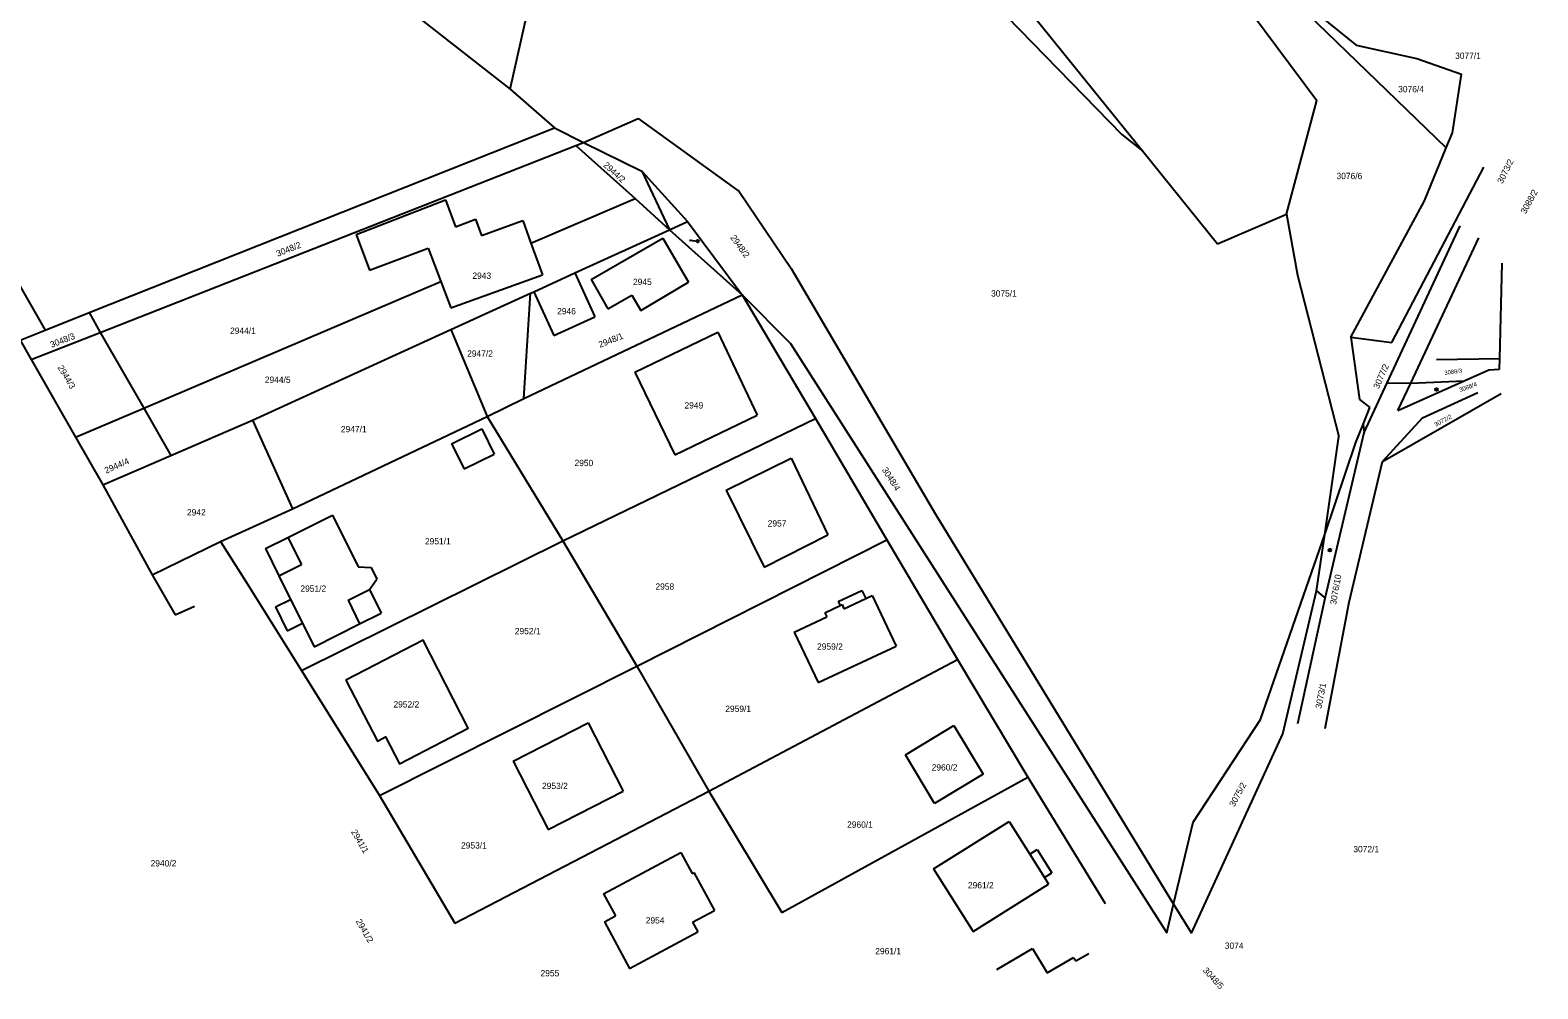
# Model space of a CAD drawing. Extents: x -722132 to -721608, y -1046877 to -1046449.
# Drawn here: x -721811.3 to -721608, y -1046875.1 to -1046745.8 of the extents above; entities that cross this region are included whole.
import ezdxf

# ---------------------------------------------------------------- set-up
doc = ezdxf.new("R2010")
doc.units = 0
for name, color, linetype in [('Vrstva 1', 7, 'Continuous'), ('Vrstva 16', 7, 'Continuous'), ('Vrstva 18', 7, 'Continuous'), ('Vrstva 19', 7, 'Continuous'), ('Vrstva 4', 7, 'Continuous'), ('Vrstva 6', 7, 'Continuous')]:
    doc.layers.add(name, color=color, linetype=linetype)

msp = doc.modelspace()

# ---------------------------------------------------------------- linework, layer by layer
at = {"layer": 'Vrstva 1'}
for p, q in [((-721693.28, -1046843.54), (-721686.72, -1046839.58)), ((-721686.72, -1046839.58), (-721682.77, -1046846.14)), ((-721689.35, -1046850.08), (-721693.28, -1046843.54)), ((-721682.77, -1046846.14), (-721689.35, -1046850.08))]:
    msp.add_line(p, q, dxfattribs=at)
for points in [[(-721796.01, -1046715.1), (-721746.59, -1046753.73)], [(-721684.82, -1046732.93), (-721661.26, -1046762.13)], [(-721746.59, -1046753.73), (-721742.65, -1046736.09)], [(-721686.47, -1046736.84), (-721664.08, -1046759.87)], [(-721651.87, -1046736.33), (-721637.78, -1046755.26)], [(-721645.76, -1046737.04), (-721620.31, -1046761.66)], [(-721645.76, -1046737.04), (-721632.49, -1046747.8)], [(-721831.5, -1046747.47), (-721809.33, -1046786.25)], [(-721632.49, -1046747.8), (-721624.3, -1046749.62)], [(-721624.3, -1046749.62), (-721618.24, -1046751.72)], [(-721619.47, -1046759.63), (-721618.24, -1046751.72)], [(-721746.59, -1046753.73), (-721740.59, -1046758.98)], [(-721641.86, -1046770.61), (-721637.78, -1046755.26)], [(-721803.37, -1046783.89), (-721740.59, -1046758.98)], [(-721740.59, -1046758.98), (-721736.69, -1046760.93)], [(-721736.69, -1046760.93), (-721729.32, -1046757.69)], [(-721729.32, -1046757.69), (-721715.68, -1046767.54)], [(-721801.9, -1046786.57), (-721737.71, -1046761.33)], [(-721737.71, -1046761.33), (-721736.69, -1046760.93)], [(-721737.71, -1046761.33), (-721729.73, -1046768.51)], [(-721736.69, -1046760.93), (-721728.84, -1046764.8)], [(-721664.08, -1046759.87), (-721661.26, -1046762.13)], [(-721620.31, -1046761.66), (-721619.47, -1046759.63)], [(-721661.26, -1046762.13), (-721651.19, -1046774.61)], [(-721623.26, -1046768.81), (-721620.31, -1046761.66)], [(-721728.84, -1046764.8), (-721722.67, -1046771.6)], [(-721627.66, -1046787.93), (-721615.25, -1046764.26)], [(-721767.37, -1046773.33), (-721755.29, -1046768.66)], [(-721755.29, -1046768.66), (-721753.94, -1046772.3)], [(-721729.73, -1046768.51), (-721725.08, -1046772.7)], [(-721715.68, -1046767.54), (-721708.67, -1046777.94)], [(-721633.18, -1046787.18), (-721623.26, -1046768.81)], [(-721753.94, -1046772.3), (-721751.24, -1046771.3)], [(-721751.24, -1046771.3), (-721750.46, -1046773.48)], [(-721750.46, -1046773.48), (-721744.88, -1046771.48)], [(-721744.88, -1046771.48), (-721743.79, -1046774.5)], [(-721651.19, -1046774.61), (-721641.86, -1046770.61)], [(-721641.86, -1046770.61), (-721640.4, -1046778.83)], [(-721767.37, -1046773.33), (-721765.54, -1046778.18)], [(-721737.88, -1046778.54), (-721725.08, -1046772.7)], [(-721725.08, -1046772.7), (-721722.67, -1046771.6)], [(-721725.08, -1046772.7), (-721715.3, -1046781.5)], [(-721722.67, -1046771.6), (-721715.3, -1046781.5)], [(-721628.27, -1046793.34), (-721618.45, -1046772.19)], [(-721765.54, -1046778.18), (-721757.63, -1046775.19)], [(-721757.63, -1046775.19), (-721755.93, -1046779.68)], [(-721743.79, -1046774.5), (-721742.23, -1046778.81)], [(-721735.65, -1046779.44), (-721725.98, -1046773.84)], [(-721725.98, -1046773.84), (-721722.54, -1046779.77)], [(-721625.1, -1046793.41), (-721615.9, -1046773.8)], [(-721613.11, -1046790.06), (-721612.77, -1046777.21)], [(-721754.57, -1046783.26), (-721742.23, -1046778.81)], [(-721743.4, -1046781.06), (-721737.88, -1046778.54)], [(-721737.88, -1046778.54), (-721735.17, -1046784.47)], [(-721735.65, -1046779.44), (-721733.41, -1046783.36)], [(-721708.67, -1046777.94), (-721689.23, -1046811.06)], [(-721640.4, -1046778.83), (-721634.82, -1046800.6)], [(-721755.93, -1046779.68), (-721754.57, -1046783.26)], [(-721754.61, -1046786.18), (-721743.84, -1046781.26)], [(-721744.72, -1046795.45), (-721743.84, -1046781.26)], [(-721744.72, -1046795.45), (-721715.3, -1046781.5)], [(-721743.84, -1046781.26), (-721743.4, -1046781.06)], [(-721743.4, -1046781.06), (-721740.69, -1046786.99)], [(-721733.41, -1046783.36), (-721730.18, -1046781.51)], [(-721730.18, -1046781.51), (-721728.97, -1046783.61)], [(-721728.97, -1046783.61), (-721722.54, -1046779.77)], [(-721715.3, -1046781.5), (-721705.42, -1046798.17)], [(-721809.33, -1046786.25), (-721803.37, -1046783.89)], [(-721803.37, -1046783.89), (-721801.9, -1046786.57)], [(-721740.69, -1046786.99), (-721735.17, -1046784.47)], [(-721812.66, -1046787.58), (-721809.33, -1046786.25)], [(-721812.66, -1046787.58), (-721811.2, -1046790.23)], [(-721811.2, -1046790.23), (-721801.9, -1046786.57)], [(-721781.34, -1046798.38), (-721754.61, -1046786.18)], [(-721729.78, -1046791.91), (-721718.58, -1046786.53)], [(-721718.58, -1046786.53), (-721713.25, -1046797.7)], [(-721633.18, -1046787.18), (-721627.66, -1046787.93)], [(-721633.18, -1046787.18), (-721632.01, -1046795.59)], [(-721811.2, -1046790.23), (-721805.2, -1046800.68)], [(-721621.64, -1046790.19), (-721613.11, -1046790.06)], [(-721617.9, -1046793.1), (-721614.58, -1046791.61)], [(-721614.58, -1046791.61), (-721613.15, -1046791.51)], [(-721613.15, -1046791.51), (-721613.11, -1046790.06)], [(-721729.78, -1046791.91), (-721724.37, -1046803.08)], [(-721631.39, -1046800.05), (-721628.27, -1046793.34)], [(-721626.83, -1046797.11), (-721617.9, -1046793.1)], [(-721626.83, -1046797.11), (-721625.1, -1046793.41)], [(-721625.1, -1046793.41), (-721617.9, -1046793.1)], [(-721749.71, -1046797.89), (-721744.72, -1046795.45)], [(-721623.53, -1046798.09), (-721616.06, -1046794.65)], [(-721775.95, -1046810.37), (-721749.71, -1046797.89)], [(-721749.71, -1046797.89), (-721739.5, -1046814.68)], [(-721724.37, -1046803.08), (-721713.25, -1046797.7)], [(-721792.35, -1046803.14), (-721781.34, -1046798.38)], [(-721781.34, -1046798.38), (-721775.95, -1046810.37)], [(-721739.5, -1046814.68), (-721705.42, -1046798.17)], [(-721705.42, -1046798.17), (-721695.78, -1046814.53)], [(-721631.54, -1046798.97), (-721631.39, -1046800.05)], [(-721628.92, -1046803.96), (-721623.53, -1046798.09)], [(-721805.2, -1046800.68), (-721801.51, -1046807.1)], [(-721636.71, -1046813.8), (-721634.82, -1046800.6)], [(-721636.64, -1046822.42), (-721631.39, -1046800.05)], [(-721801.51, -1046807.1), (-721792.35, -1046803.14)], [(-721717.46, -1046807.83), (-721708.66, -1046803.51)], [(-721708.66, -1046803.51), (-721703.72, -1046813.87)], [(-721633.43, -1046822.95), (-721628.92, -1046803.96)], [(-721801.51, -1046807.1), (-721794.88, -1046819.26)], [(-721717.46, -1046807.83), (-721712.34, -1046818.2)], [(-721785.64, -1046814.77), (-721775.95, -1046810.37)], [(-721776.56, -1046814.2), (-721770.53, -1046811.2)], [(-721770.53, -1046811.2), (-721767.09, -1046818.16)], [(-721689.23, -1046811.06), (-721657.09, -1046863.66)], [(-721779.59, -1046815.71), (-721776.56, -1046814.2)], [(-721712.34, -1046818.2), (-721703.72, -1046813.87)], [(-721645.36, -1046838.78), (-721636.71, -1046813.8)], [(-721637.8, -1046821.42), (-721636.71, -1046813.8)], [(-721794.88, -1046819.26), (-721785.64, -1046814.77)], [(-721785.64, -1046814.77), (-721782.17, -1046820.29)], [(-721779.59, -1046815.71), (-721777.77, -1046819.38)], [(-721774.72, -1046832.15), (-721739.5, -1046814.68)], [(-721739.5, -1046814.68), (-721729.49, -1046831.56)], [(-721729.49, -1046831.56), (-721695.78, -1046814.53)], [(-721695.78, -1046814.53), (-721686.26, -1046830.68)], [(-721767.09, -1046818.16), (-721765.35, -1046818.25)], [(-721765.35, -1046818.25), (-721764.58, -1046819.82)], [(-721794.88, -1046819.26), (-721791.78, -1046824.67)], [(-721782.17, -1046820.29), (-721774.72, -1046832.15)], [(-721777.77, -1046819.38), (-721776.2, -1046822.56)], [(-721765.56, -1046821.25), (-721764.58, -1046819.82)], [(-721765.56, -1046821.25), (-721763.99, -1046824.43)], [(-721702.35, -1046822.86), (-721699.14, -1046821.36)], [(-721699.14, -1046821.36), (-721698.63, -1046822.44)], [(-721698.63, -1046822.44), (-721697.74, -1046822.02)], [(-721697.74, -1046822.02), (-721694.5, -1046828.86)], [(-721642.34, -1046840.71), (-721637.8, -1046821.42)], [(-721637.8, -1046821.42), (-721636.64, -1046822.42)], [(-721778.26, -1046823.58), (-721776.2, -1046822.56)], [(-721778.26, -1046823.58), (-721776.66, -1046826.81)], [(-721704.14, -1046824.36), (-721702.09, -1046823.4)], [(-721704.14, -1046824.36), (-721703.88, -1046824.91)], [(-721702.35, -1046822.86), (-721702.09, -1046823.4)], [(-721640.33, -1046839.32), (-721636.64, -1046822.42)], [(-721636.63, -1046839.98), (-721633.43, -1046822.95)], [(-721776.66, -1046826.81), (-721774.6, -1046825.79)], [(-721774.6, -1046825.79), (-721773.04, -1046828.95)], [(-721773.04, -1046828.95), (-721766.89, -1046825.88)], [(-721766.89, -1046825.88), (-721763.99, -1046824.43)], [(-721708.28, -1046826.98), (-721703.88, -1046824.91)], [(-721768.76, -1046833.45), (-721764.48, -1046841.67), (-721763.41, -1046841.12), (-721761.51, -1046844.76), (-721752.23, -1046839.92), (-721758.34, -1046828.08), (-721768.76, -1046833.45)], [(-721708.28, -1046826.98), (-721705.05, -1046833.79)], [(-721705.05, -1046833.79), (-721694.5, -1046828.86)], [(-721774.72, -1046832.15), (-721764.2, -1046849)], [(-721764.2, -1046849), (-721729.49, -1046831.56)], [(-721729.49, -1046831.56), (-721719.77, -1046848.42)], [(-721719.77, -1046848.42), (-721686.26, -1046830.68)], [(-721686.26, -1046830.68), (-721676.74, -1046846.55)], [(-721746.2, -1046844.38), (-721736.06, -1046839.2)], [(-721736.06, -1046839.2), (-721731.34, -1046848.45)], [(-721654.46, -1046852.63), (-721645.36, -1046838.78)], [(-721654.68, -1046867.6), (-721642.34, -1046840.71)], [(-721746.2, -1046844.38), (-721741.48, -1046853.62)], [(-721709.96, -1046864.8), (-721676.74, -1046846.55)], [(-721676.74, -1046846.55), (-721666.33, -1046863.6)], [(-721741.48, -1046853.62), (-721731.34, -1046848.45)], [(-721719.77, -1046848.42), (-721709.96, -1046864.8)], [(-721689.47, -1046858.91), (-721679.27, -1046852.51)], [(-721679.27, -1046852.51), (-721676.51, -1046856.91)], [(-721657.09, -1046863.66), (-721654.46, -1046852.63)], [(-721733.98, -1046862.27), (-721723.58, -1046856.69)], [(-721723.58, -1046856.69), (-721722.05, -1046859.54)], [(-721676.51, -1046856.91), (-721675.52, -1046856.29)], [(-721675.52, -1046856.29), (-721673.53, -1046859.46)], [(-721689.47, -1046858.91), (-721684.13, -1046867.38)], [(-721722.05, -1046859.54), (-721721.79, -1046859.4)], [(-721721.79, -1046859.4), (-721719.04, -1046864.53)], [(-721684.13, -1046867.38), (-721673.95, -1046860.99)], [(-721674.52, -1046860.08), (-721673.53, -1046859.46)], [(-721674.52, -1046860.08), (-721673.95, -1046860.99)], [(-721733.98, -1046862.27), (-721732.39, -1046865.25)], [(-721721.98, -1046866.11), (-721719.04, -1046864.53)], [(-721657.09, -1046863.66), (-721654.68, -1046867.6)], [(-721733.87, -1046866.04), (-721732.39, -1046865.25)], [(-721733.87, -1046866.04), (-721730.49, -1046872.35)], [(-721721.98, -1046866.11), (-721721.28, -1046867.41)], [(-721730.49, -1046872.35), (-721721.28, -1046867.41)], [(-721680.93, -1046872.47), (-721676.11, -1046869.64)], [(-721676.11, -1046869.64), (-721674.17, -1046872.96)], [(-721674.17, -1046872.96), (-721670.58, -1046870.86)], [(-721670.58, -1046870.86), (-721670.3, -1046871.33)], [(-721670.3, -1046871.33), (-721668.55, -1046870.32)]]:
    msp.add_lwpolyline(points, dxfattribs=at)
at = {"layer": 'Vrstva 16'}
for points in [[(-721722.38, -1046774.12), (-721721.3, -1046774.23)], [(-721621.88, -1046794.22), (-721621.63, -1046794.26)], [(-721636.15, -1046815.75), (-721636.01, -1046815.94)]]:
    msp.add_lwpolyline(points, dxfattribs=at)
for centre in [(-721721.3, -1046774.23), (-721621.63, -1046794.26), (-721636.01, -1046815.94)]:
    msp.add_circle(centre, 0.175, dxfattribs=at)
at = {"layer": 'Vrstva 4'}
for points in [[(-721728.84, -1046764.8), (-721725.08, -1046772.7)], [(-721754.49, -1046801.57), (-721750.43, -1046799.56)], [(-721750.43, -1046799.56), (-721748.74, -1046802.98)], [(-721754.49, -1046801.57), (-721752.8, -1046804.95)], [(-721752.8, -1046804.95), (-721748.74, -1046802.98)], [(-721776.56, -1046814.2), (-721774.74, -1046817.88)], [(-721777.77, -1046819.38), (-721774.74, -1046817.88)], [(-721768.46, -1046822.69), (-721765.56, -1046821.25)], [(-721776.2, -1046822.56), (-721774.6, -1046825.79)], [(-721768.46, -1046822.69), (-721766.89, -1046825.88)], [(-721702.09, -1046823.4), (-721701.82, -1046823.27)], [(-721701.82, -1046823.27), (-721701.56, -1046823.82)], [(-721701.56, -1046823.82), (-721698.63, -1046822.44)], [(-721676.51, -1046856.91), (-721674.52, -1046860.08)]]:
    msp.add_lwpolyline(points, dxfattribs=at)
at = {"layer": 'Vrstva 6'}
for points in [[(-721743.79, -1046774.5), (-721729.73, -1046768.51)], [(-721796.02, -1046796.77), (-721755.93, -1046779.68)], [(-721715.3, -1046781.5), (-721708.76, -1046788.03)], [(-721801.9, -1046786.57), (-721796.02, -1046796.77)], [(-721754.61, -1046786.18), (-721749.71, -1046797.89)], [(-721708.76, -1046788.03), (-721658.02, -1046867.55)], [(-721628.27, -1046793.34), (-721625.1, -1046793.41)], [(-721632.01, -1046795.59), (-721630.64, -1046796.7)], [(-721628.92, -1046803.96), (-721612.93, -1046794.81)], [(-721805.2, -1046800.68), (-721796.02, -1046796.77)], [(-721796.02, -1046796.77), (-721792.35, -1046803.14)], [(-721631.54, -1046798.97), (-721630.64, -1046796.7)], [(-721632.5, -1046801.41), (-721631.54, -1046798.97)], [(-721636.71, -1046813.8), (-721632.5, -1046801.41)], [(-721791.78, -1046824.67), (-721789.17, -1046823.48)], [(-721754.04, -1046866.24), (-721719.77, -1046848.42)], [(-721764.2, -1046849), (-721754.04, -1046866.24)], [(-721658.02, -1046867.55), (-721657.09, -1046863.66)]]:
    msp.add_lwpolyline(points, dxfattribs=at)

# ---------------------------------------------------------------- texts
at = {"layer": 'Vrstva 16'}
for s, height, rotation, p in [('2948/2', 0.85, 305.9069, (-721716.94, -1046773.77)), ('3088/4', 0.595, 19.9892, (-721618.46, -1046794.62)), ('3076/10', 0.85, 79.8324, (-721635.18, -1046823.33))]:
    msp.add_text(s, height=height, rotation=rotation, dxfattribs=at).set_placement(p)
at = {"layer": 'Vrstva 18'}
for s, height, p in [('3077/1', 0.85, (-721619.12, -1046749.66)), ('3076/4', 0.85, (-721626.8, -1046754.16)), ('3076/6', 0.85, (-721635.12, -1046765.88)), ('2948/2', 0.1, (-721722.38, -1046774.12)), ('3075/1', 0.85, (-721681.72, -1046781.72)), ('2944/1', 0.85, (-721784.37, -1046786.75)), ('2947/2', 0.85, (-721752.39, -1046789.83)), ('2944/5', 0.85, (-721779.68, -1046793.36)), ('2947/1', 0.85, (-721769.42, -1046800.02)), ('2950', 0.85, (-721737.91, -1046804.59)), ('2942', 0.85, (-721790.18, -1046811.25)), ('2951/1', 0.85, (-721758.08, -1046815.15)), ('3076/10', 0.1, (-721636.15, -1046815.75)), ('2958', 0.85, (-721726.99, -1046821.26)), ('2952/1', 0.85, (-721745.96, -1046827.27)), ('2959/1', 0.85, (-721717.57, -1046837.74)), ('2960/1', 0.85, (-721701.14, -1046853.37)), ('2953/1', 0.85, (-721753.21, -1046856.17)), ('3072/1', 0.85, (-721632.85, -1046856.67)), ('2940/2', 0.85, (-721795.09, -1046858.59)), ('3074', 0.85, (-721650.19, -1046869.7)), ('2961/1', 0.85, (-721697.34, -1046870.43)), ('2955', 0.85, (-721742.49, -1046873.41))]:
    msp.add_text(s, height=height, dxfattribs=at).set_placement(p)
for s, height, rotation, p in [('3073/2', 0.85, 63.4139, (-721612.74, -1046766.57)), ('2944/2', 0.85, 317.6993, (-721734.09, -1046764.1)), ('3088/2', 0.85, 61.5479, (-721609.59, -1046770.64)), ('3048/2', 0.85, 21.5147, (-721777.94, -1046776.36)), ('3048/3', 0.85, 21.5147, (-721808.44, -1046788.65)), ('2948/1', 0.85, 21.6708, (-721734.47, -1046788.64)), ('2944/3', 0.85, 300.7302, (-721807.67, -1046791.28)), ('3077/2', 0.85, 66.2913, (-721629.42, -1046794.24)), ('3088/3', 0.57, 7.9457, (-721620.53, -1046792.3)), ('3088/4', 0.1, 355.9507, (-721621.88, -1046794.22)), ('3072/2', 0.595, 28.2422, (-721621.72, -1046799.29)), ('2944/4', 0.85, 23.8283, (-721801.08, -1046805.62)), ('3048/4', 0.85, 302.5229, (-721696.48, -1046805.08)), ('3073/1', 0.85, 79.317, (-721637.15, -1046837.35)), ('3075/2', 0.85, 61.5947, (-721648.9, -1046850.62)), ('2941/1', 0.85, 300.1316, (-721768.08, -1046853.91)), ('2941/2', 0.85, 300.2843, (-721767.45, -1046865.99)), ('3048/5', 0.85, 312.3645, (-721653.21, -1046872.66))]:
    msp.add_text(s, height=height, rotation=rotation, dxfattribs=at).set_placement(p)
at = {"layer": 'Vrstva 19'}
for s, p in [('2943', (-721751.68, -1046779.33)), ('2945', (-721730.02, -1046780.16)), ('2946', (-721740.25, -1046784.11)), ('2949', (-721723.07, -1046796.82)), ('2957', (-721711.85, -1046812.74)), ('2951/2', (-721774.88, -1046821.54)), ('2959/2', (-721705.19, -1046829.35)), ('2952/2', (-721762.33, -1046837.15)), ('2960/2', (-721689.73, -1046845.65)), ('2953/2', (-721742.29, -1046848.15)), ('2961/2', (-721684.84, -1046861.55)), ('2954', (-721728.3, -1046866.28))]:
    msp.add_text(s, height=0.85, dxfattribs=at).set_placement(p)

doc.saveas('drawing.dxf')
